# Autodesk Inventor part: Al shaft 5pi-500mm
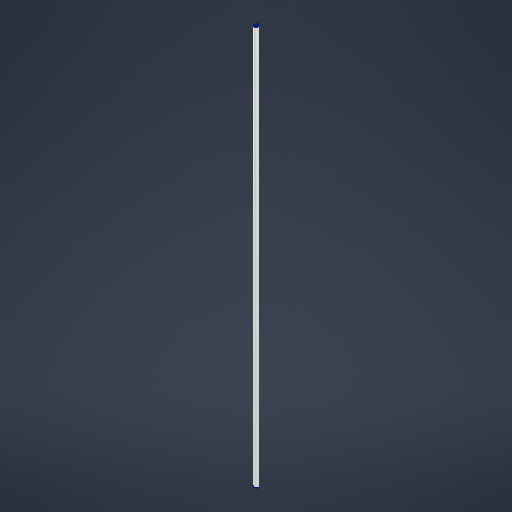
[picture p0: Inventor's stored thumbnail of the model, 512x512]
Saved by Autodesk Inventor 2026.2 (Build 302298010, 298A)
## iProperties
Created: 2026-04
Part Number: Al shaft 5pi-500mm
Material: 알루미늄 6061
Document SubType Name: Modeling
Designer: work
Density: 2.7 g/cm^3
Appearance: 알루미늄 - 평지
Author: work
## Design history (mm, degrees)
sketch "스케치1"
  geometry: C1 r 2.5 at (0, 0); C2 r 1.25 at (0, 0); 1 further point
  constraints: 2 centre point, 2 coincident
  dimensions: "d0" = 5 diameter of C1; "d1" = 2.5 diameter of C2
extrude "돌출1" new body sketch "스케치1" distance "d2" = 500; taper "d3" = 0 deg
chamfer "모따기1" distance "d4" = 0.25; stored, may be unused: second distance "d5" = 2, angle "d6" = 45 deg
node "솔리드1"
